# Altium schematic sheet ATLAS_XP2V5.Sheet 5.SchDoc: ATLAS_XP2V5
size 558 x 431 mm; Organization: IMP Automatika d.o.o.; Revision: V5
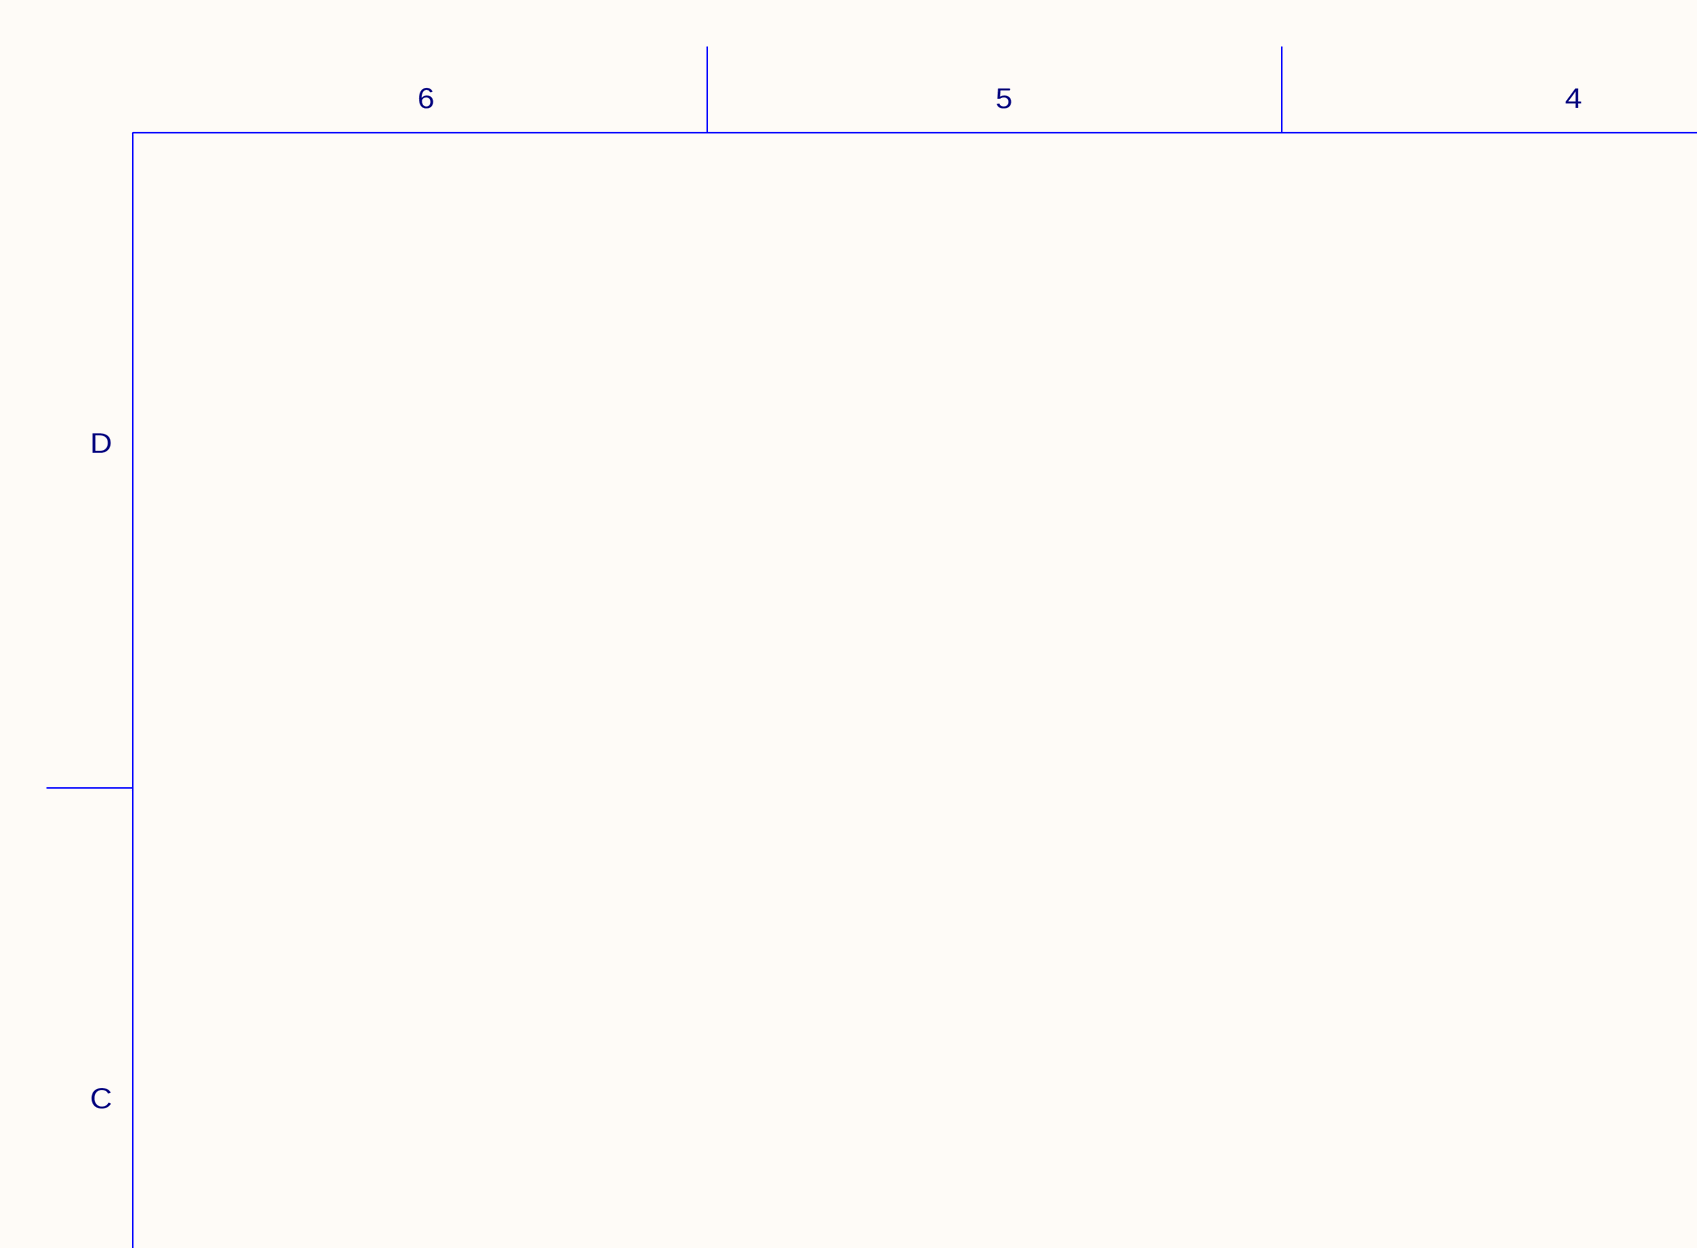
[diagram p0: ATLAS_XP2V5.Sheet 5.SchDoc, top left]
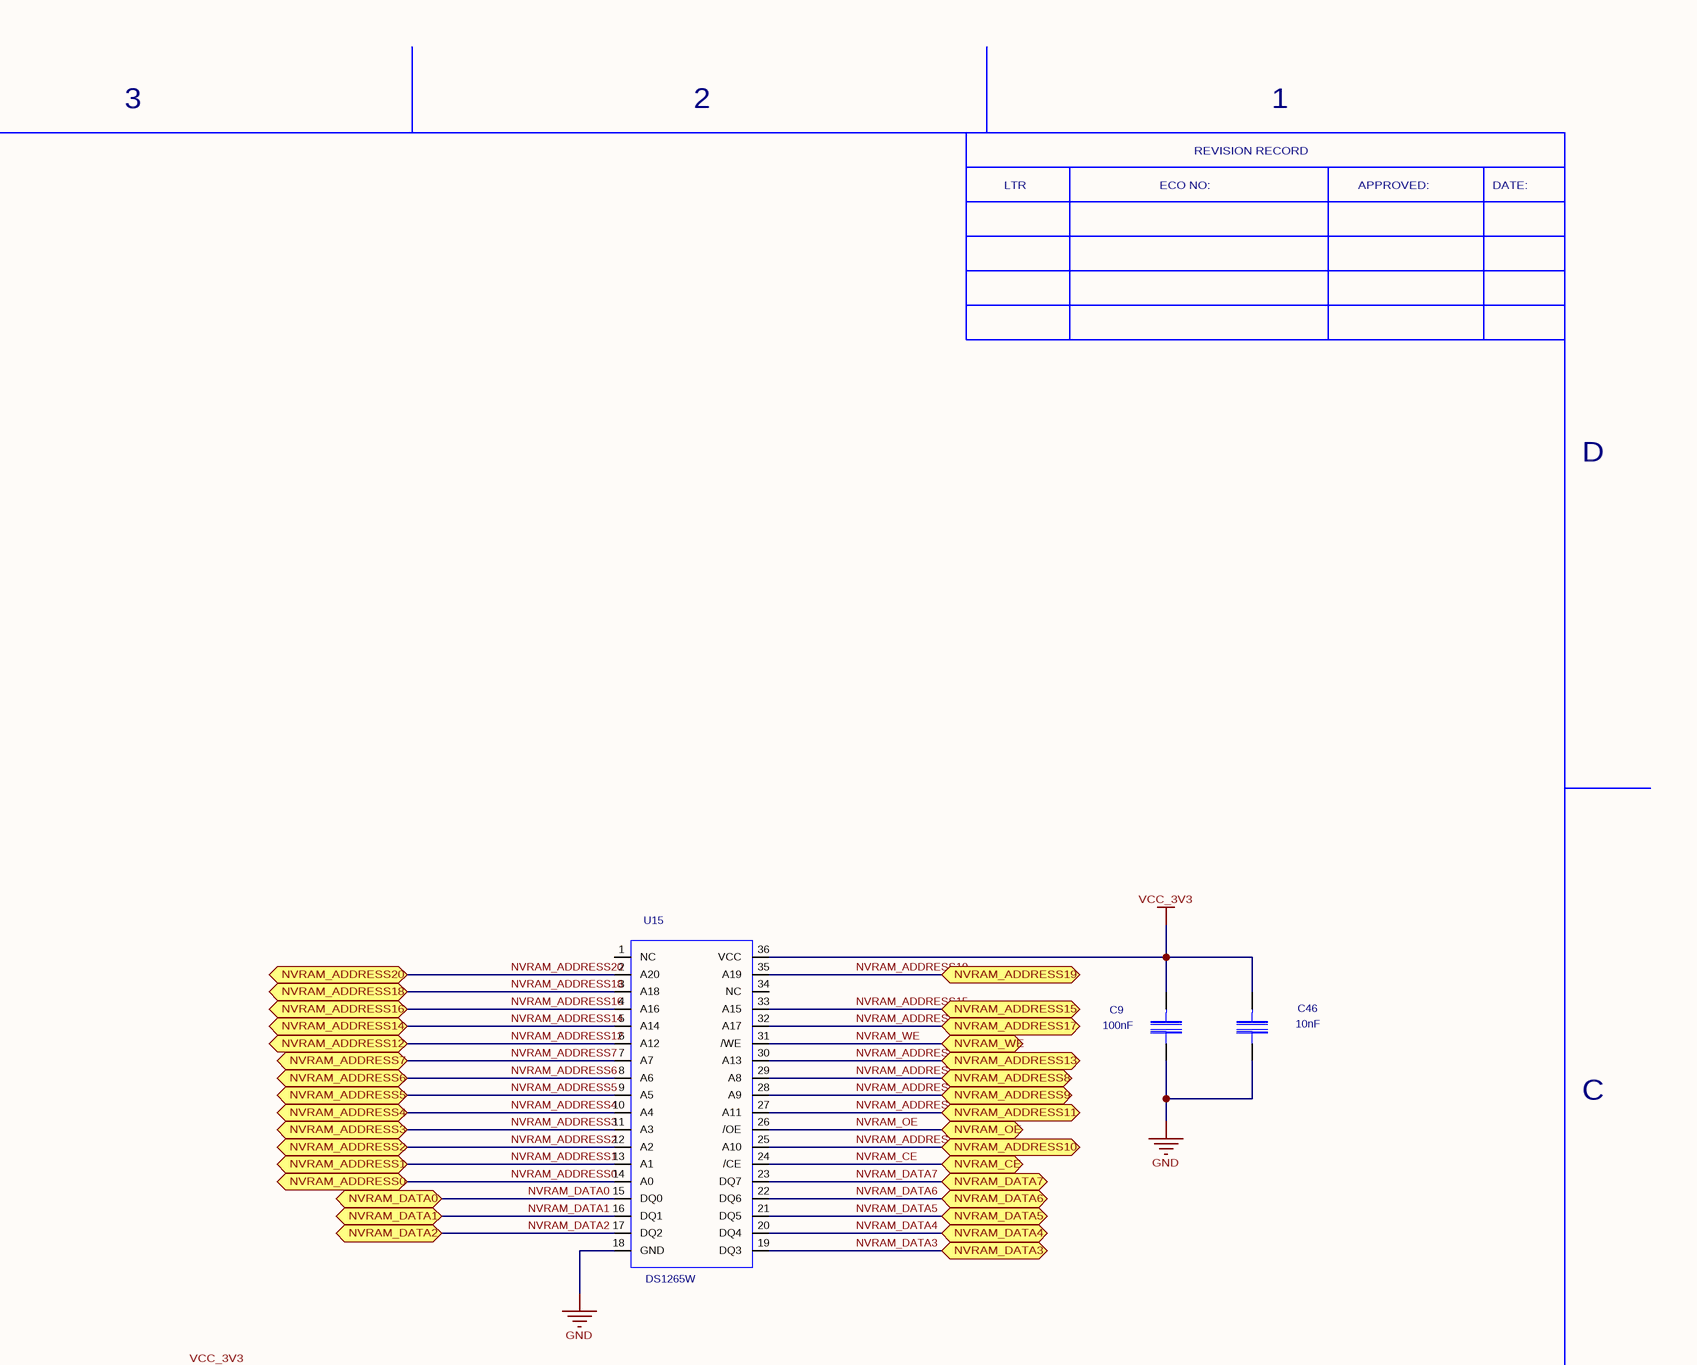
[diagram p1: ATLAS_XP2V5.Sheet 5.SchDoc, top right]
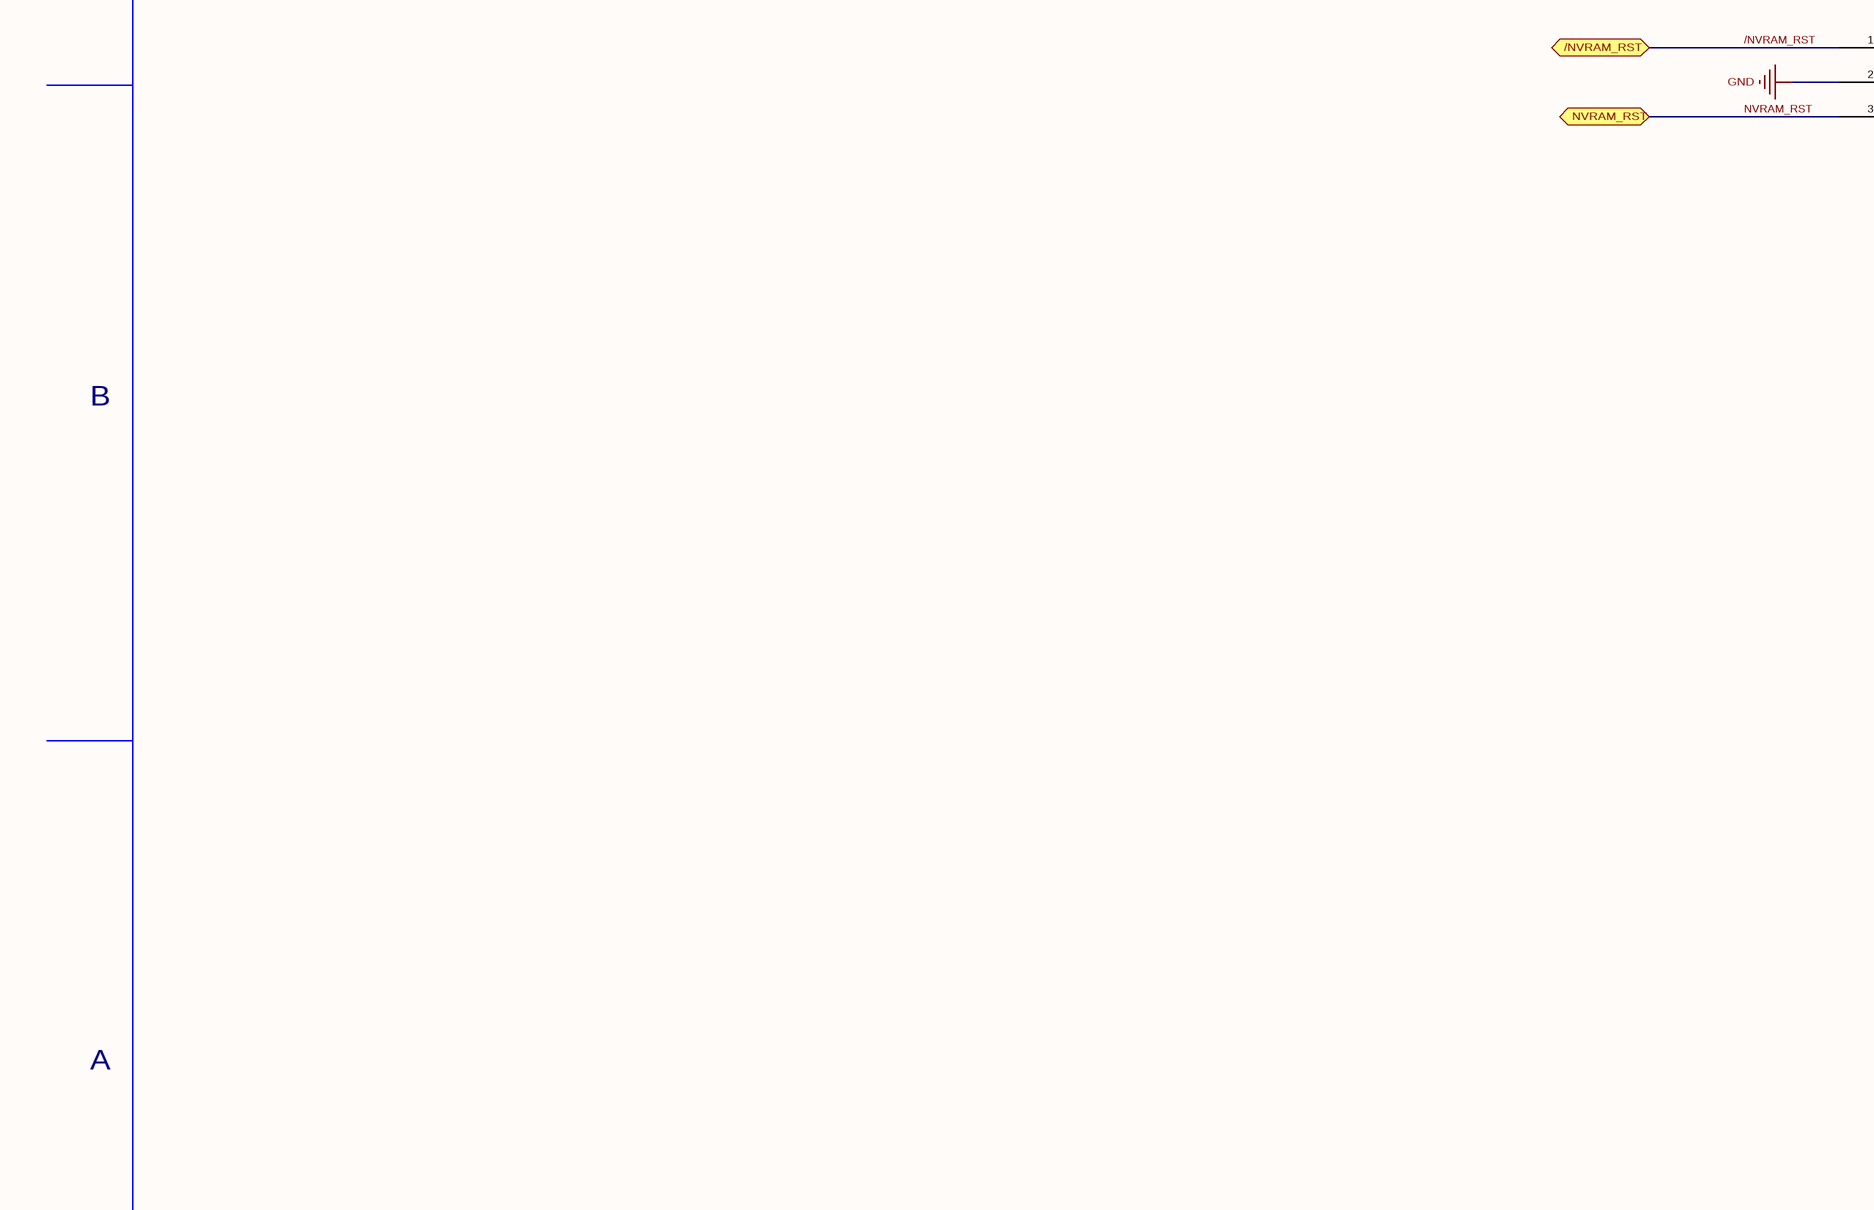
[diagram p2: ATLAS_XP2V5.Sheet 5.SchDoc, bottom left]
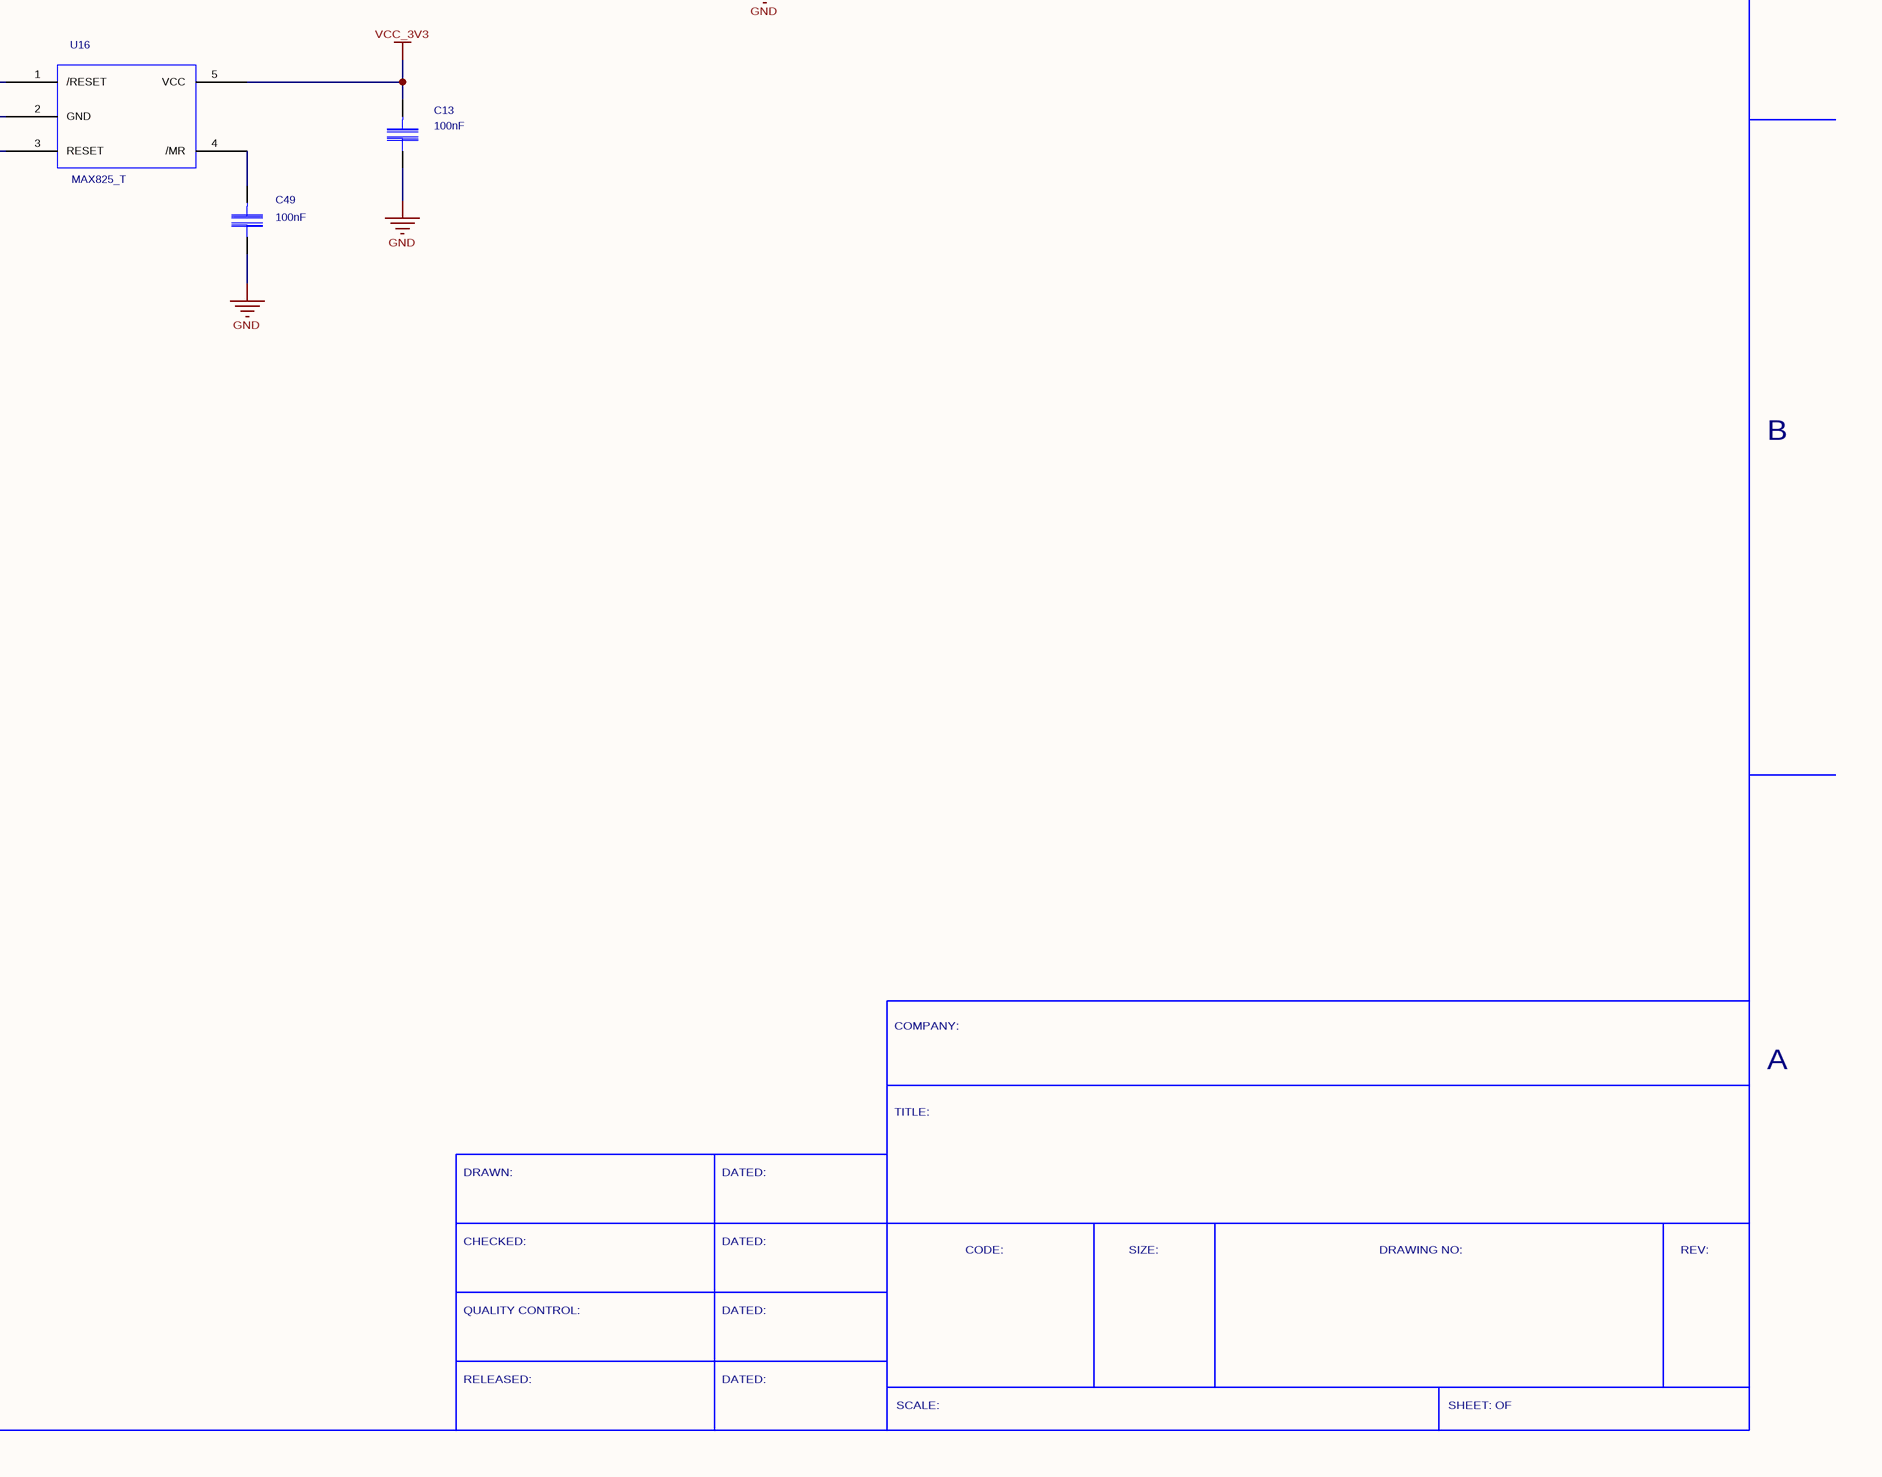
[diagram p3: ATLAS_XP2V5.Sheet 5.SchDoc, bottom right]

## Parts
C9  value 100nF  [SM/C_0805]  (hidden comment: C)
C13  value 100nF  [SM/C_0805]  (hidden comment: C)
C46  value 10nF  [SM/C_0805]  (hidden comment: C)
C49  value 100nF  [SM/C_0805]  (hidden comment: C)
U15  DS1265W  [DIP.100/36/W.600/L1.850]
U16  MAX825_T  [SOT23_5_MILOS_REV4]

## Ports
/NVRAM_RST (bidir), NVRAM_ADDRESS0 (bidir), NVRAM_ADDRESS1 (bidir), NVRAM_ADDRESS2 (bidir), NVRAM_ADDRESS3 (bidir), NVRAM_ADDRESS4 (bidir), NVRAM_ADDRESS5 (bidir), NVRAM_ADDRESS6 (bidir), NVRAM_ADDRESS7 (bidir), NVRAM_ADDRESS8 (bidir), NVRAM_ADDRESS9 (bidir), NVRAM_ADDRESS10 (bidir), NVRAM_ADDRESS11 (bidir), NVRAM_ADDRESS12 (bidir), NVRAM_ADDRESS13 (bidir), NVRAM_ADDRESS14 (bidir), NVRAM_ADDRESS15 (bidir), NVRAM_ADDRESS16 (bidir), NVRAM_ADDRESS17 (bidir), NVRAM_ADDRESS18 (bidir), NVRAM_ADDRESS19 (bidir), NVRAM_ADDRESS20 (bidir), NVRAM_CE (bidir), NVRAM_DATA0 (bidir), NVRAM_DATA1 (bidir), NVRAM_DATA2 (bidir), NVRAM_DATA3 (bidir), NVRAM_DATA4 (bidir), NVRAM_DATA5 (bidir), NVRAM_DATA6 (bidir), NVRAM_DATA7 (bidir), NVRAM_OE (bidir), NVRAM_RST (bidir), NVRAM_WE (bidir)

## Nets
GND: C9.2 C13.2 C46.2 C49.2 U15.18(GND) U16.2(GND)
VCC_3V3: C9.1 C13.1 C46.1 U15.36(VCC) U16.5(VCC)
/NVRAM_RST: U16.1(/RESET) ; port /NVRAM_RST
NVRAM_ADDRESS0: U15.14(A0) ; port NVRAM_ADDRESS0
NVRAM_ADDRESS1: U15.13(A1) ; port NVRAM_ADDRESS1
NVRAM_ADDRESS2: U15.12(A2) ; port NVRAM_ADDRESS2
NVRAM_ADDRESS3: U15.11(A3) ; port NVRAM_ADDRESS3
NVRAM_ADDRESS4: U15.10(A4) ; port NVRAM_ADDRESS4
NVRAM_ADDRESS5: U15.9(A5) ; port NVRAM_ADDRESS5
NVRAM_ADDRESS6: U15.8(A6) ; port NVRAM_ADDRESS6
NVRAM_ADDRESS7: U15.7(A7) ; port NVRAM_ADDRESS7
NVRAM_ADDRESS8: U15.29(A8) ; port NVRAM_ADDRESS8
NVRAM_ADDRESS9: U15.28(A9) ; port NVRAM_ADDRESS9
NVRAM_ADDRESS10: U15.25(A10) ; port NVRAM_ADDRESS10
NVRAM_ADDRESS11: U15.27(A11) ; port NVRAM_ADDRESS11
NVRAM_ADDRESS12: U15.6(A12) ; port NVRAM_ADDRESS12
NVRAM_ADDRESS13: U15.30(A13) ; port NVRAM_ADDRESS13
NVRAM_ADDRESS14: U15.5(A14) ; port NVRAM_ADDRESS14
NVRAM_ADDRESS15: U15.33(A15) ; port NVRAM_ADDRESS15
NVRAM_ADDRESS16: U15.4(A16) ; port NVRAM_ADDRESS16
NVRAM_ADDRESS17: U15.32(A17) ; port NVRAM_ADDRESS17
NVRAM_ADDRESS18: U15.3(A18) ; port NVRAM_ADDRESS18
NVRAM_ADDRESS19: U15.35(A19) ; port NVRAM_ADDRESS19
NVRAM_ADDRESS20: U15.2(A20) ; port NVRAM_ADDRESS20
NVRAM_CE: U15.24(/CE) ; port NVRAM_CE
NVRAM_DATA0: U15.15(DQ0) ; port NVRAM_DATA0
NVRAM_DATA1: U15.16(DQ1) ; port NVRAM_DATA1
NVRAM_DATA2: U15.17(DQ2) ; port NVRAM_DATA2
NVRAM_DATA3: U15.19(DQ3) ; port NVRAM_DATA3
NVRAM_DATA4: U15.20(DQ4) ; port NVRAM_DATA4
NVRAM_DATA5: U15.21(DQ5) ; port NVRAM_DATA5
NVRAM_DATA6: U15.22(DQ6) ; port NVRAM_DATA6
NVRAM_DATA7: U15.23(DQ7) ; port NVRAM_DATA7
NVRAM_OE: U15.26(/OE) ; port NVRAM_OE
NVRAM_RST: U16.3(RESET) ; port NVRAM_RST
NVRAM_WE: U15.31(/WE) ; port NVRAM_WE
NetC49_1: C49.1 U16.4(/MR)

Not connected (* = marked no-connect by the designer): U15 1(NC) 34(NC)

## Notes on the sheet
- 6
- 5
- 4
- 3
- 2
- 1
- LTR
- ECO NO:
- REVISION RECORD
- APPROVED:
- DATE:
- D
- C
- B
- COMPANY:
- A
- TITLE:
- DRAWN:
- DATED:
- CHECKED:
- CODE:
- SIZE:
- DRAWING NO:
- REV:
- QUALITY CONTROL:
- RELEASED:
- SCALE:
- SHEET: OF

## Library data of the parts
C9 C13 C46 C49 = C: Source_Path: D:\ORCADWIN\CAPTURE\ATP_LATT_01\ATP_00.OLB; SDTSourceLibName: C:\WINDOWS\TEMP\ATP_00.LIB
U15 = DS1265W: Source_Path: E:\MILOS\PROJECTS\ATLAS_XP2V3\DALLAS.OLB
U16 = MAX825_T: Source_Path: E:\MILOS\PROJECTS\ATLAS_XP2V3\ATLASXP.OLB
